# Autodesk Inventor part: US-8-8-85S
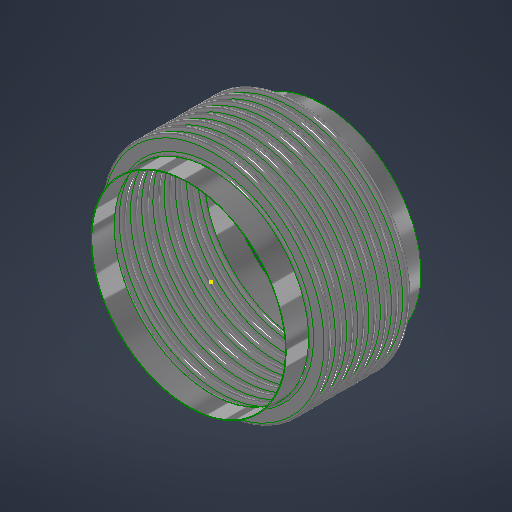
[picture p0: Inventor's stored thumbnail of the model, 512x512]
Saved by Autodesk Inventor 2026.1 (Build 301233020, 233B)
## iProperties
Category: 22 GA (0.030 THICK)
RuleStatus: InUse
Created: 2026-07
Part Number: US-8-8-85S
Project: =STOCK BELLOWS: <Stock Number><SFILL>
Material: ASTM A240-304
Description: =STOCK BELLOWS: <Stock Number>, <SID_> I.D., <SOD_> O.D., <SPLY_> PLY, <Category>, <SNET_CONS> CONS.<PITCH_><STANGENT_> TANGENT<SFILL>
Document SubType Name: Sheet Metal
Designer: LC
Stock Number: U.S-8-8-85S
Surface Area: 659.127 cm^2
Volume: 56.61 cm^3
Sheet Metal Rule: Default
Appearance: STAINLESS STEEL
NET_TUBE: 3.428
COUNTER: 1.500
PBAR: 1.214
PSET: 5.356
PLY: 2
CONS: 2
THK: 0.036
ID: 4.500
OD: 5.500
CONS_: 2
TANGENT: 0.500
PITCH: 0.375
BELLOWS_UPSET: 0.000
NET_CONS: 2
S_CONS: 0
Description_Units: 0
ID_M: 114.30 mm
OD_M: 139.70 mm
THK_M: 0.91 mm
ID_U: 4.500 in
OD_U: 5.500 in
THK_U: 0.036 in
TANGENT2: 0.500
d79: 1.000
d82: 1.000
d83: 26.000
d84: 24.000
d80: 2.571
d81: 10
SID: 2.375
SCONS_: 8
SPITCH: 0.250
SBELLOWS_UPSET: 0.000
SNET_CONS: 8
SS_CONS: 0
SCONS: 8
d174: 8
d177: 0.018
d178: 2.375
d179: 3.000
d180: 0.375
d181: 1.000
d182: 0.000
d190: 8
d191: 1
d192: 1
d193: 8
d194: 0
PART_NUMBER: U.S-8-8-85S
PRESSURE: 85
SIZE: 8.00
STANGENT_: 1.000
d214: 8
d217: 0.030
d218: 6.625
d219: 8.125
d220: 0.500
d221: 1.000
d222: 0.000
d230: 8
d231: 1
d232: 1
d233: 8
d234: 0
STANGENT: 4.000
SPLY_: 1
STHK_: 0.030
SID_: 8.625
SOD_: 10.125
SPITCH_: 0.500
STANGENT__: 1.000
SBELLOWS_UPSET_: 0.000
SDIFF_TAN: 1.000
TAN_TO_TAN: 0.750 in
d252: 2
d275: 2
d287: 0.050
d289: 0.500
d290: 0.000
d263: 2
d265: 1
d268: 2
d269: 0
d286: 2
d288: 1
d291: 2
d292: 0
SOD_NECK: 8 11/16
CFILL: .
SFILL: .
PITCH_: =, <SPITCH_> PITCH,
SREROLL: 0.750
MATTABLE: 20 GA (0.036 THICK)
MESH: ,
CSECT: 2
Author: LC
Keywords: 20 GA (0.036 THICK)
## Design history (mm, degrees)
sketch "Sketch2"
  geometry: L1 (0, -183.595)-(0, 600.956) reference; L2 (58.979, 0)-(57.15, 0); L3 (60.446, -1.467)-(66.554, -1.467); L4 (60.446, -3.296)-(66.554, -3.296); L5 (66.554, -8.058)-(60.446, -8.058); L6 (66.554, -6.229)-(60.446, -6.229); L7 (58.979, -9.525)-(57.15, -9.525); L8 (60.446, 0)-(60.446, -9.525); L9 (66.554, -4.762)-(69.85, -4.763); L10 (57.15, 0)-(57.15, -9.525); L11 (20.376, 102.841)-(20.376, 101.926); L12 (58.262, 488.877)-(58.262, 349.177); L13 (58.262, 479.352)-(58.262, 339.652); L14 (93.133, -58.817)-(93.133, -71.517); L15 (118.746, -66.401)-(118.746, -66.401); L16 (66.554, -6.229)-(66.554, -8.058); L17 (60.446, -6.229)-(60.446, -8.058); L18 (60.446, -7.144)-(66.554, -7.144); L19 (69.85, 0)-(69.85, -9.525); L20 (-66.554, -6.229)-(-66.554, -8.058); L21 (-66.554, -1.467)-(-60.446, -1.467); L22 (-66.554, -3.296)-(-60.446, -3.296); L23 (-60.446, -6.229)-(-66.554, -6.229); L24 (-66.554, -7.144)-(-60.446, -7.144); L25 (-60.446, -8.058)-(-66.554, -8.058); L26 (-60.446, -6.229)-(-60.446, -8.058); L27 (-57.15, -2.522)-(-57.15, -12.047); L28 (-60.446, -4.763)-(-57.15, -4.763); L29 (-66.554, 3.828)-(-66.554, -9.525); L30 (-68.021, 0)-(-69.85, 0); L31 (-69.85, 0)-(-69.85, -9.525); L32 (-68.021, -9.525)-(-69.85, -9.525); A1 r 1.467 centre (60.446, 0) between (58.979, 0) and (60.446, -1.467); A2 r 3.296 centre (60.446, 0) between (57.15, 0) and (60.446, -3.296); A3 r 3.296 centre (66.554, -4.762) between (66.554, -8.058) and (66.554, -1.467); A4 r 1.467 centre (66.554, -4.762) between (66.554, -6.229) and (66.554, -3.296); A5 r 1.467 centre (60.446, -9.525) between (60.446, -8.058) and (58.979, -9.525); A6 r 3.296 centre (60.446, -9.525) between (60.446, -6.229) and (57.15, -9.525); A7 r 2.381 centre (66.554, -4.762) between (66.554, -7.144) and (68.936, -4.762); A8 r 2.381 centre (60.446, -9.525) between (60.446, -7.144) and (58.064, -9.525); A9 r 1.467 centre (-66.554, -9.525) between (-66.554, -8.058) and (-68.021, -9.525); A10 r 1.467 centre (-60.446, -4.763) between (-60.446, -6.229) and (-60.446, -3.296); A11 r 2.381 centre (-60.446, -4.763) between (-60.446, -7.144) and (-58.064, -4.763); A12 r 3.296 centre (-60.446, -4.763) between (-60.446, -8.058) and (-60.446, -1.467); A13 r 2.381 centre (-66.554, -9.525) between (-66.554, -7.144) and (-68.936, -9.525); A14 r 3.296 centre (-66.554, -9.525) between (-66.554, -6.229) and (-69.85, -9.525); A15 r 1.467 centre (-66.554, 0) between (-68.021, 0) and (-66.554, -1.467); A16 r 3.296 centre (-66.554, 0) between (-69.85, 0) and (-66.554, -3.296); 10 further points
  constraints: 62 end point, 38 point on circle, 20 tangent, 16 centre point, 12 parallel, 9 midpoint, 7 vertical, 6 coincident, 6 concentric, 6 point on line, 4 equal radius, 4 perpendicular, 3 horizontal, 1 collinear, 1 horizontal alignment, 10 other
  dimensions: "THK" = 0.9144 distance of L11.start L11.end; "ID" = 114.3 distance of L11.end point (20.376, -12.374); "OD" = 139.7 distance of L12.start L12.end; "PITCH" = 9.525 distance of L12.start L13.start; "TANGENT" = 12.7 distance of L14.start L14.end; "BELLOWS_UPSET" = 0 distance of L15.start L15.end; "d43" = 114.3 diameter of L10 L1 (= ID); "d44" = 139.7 diameter of L9.end L1 (= OD); "d45" = 1.8288 distance between parallel lines of L5 L6 (computed from THK, PLY); "d46" = 3.29565 radius of A3 (computed from PITCH, THK, PLY); "UPSET_PITCH" = 9.525 distance of L2.end L7.end (derived); "SIDEWALL_ANGLE" = 0 deg angle of L3 L9 (derived); "CON_GAP" = 2.9337 distance of point (60.446, -6.229) point (60.446, -3.296) (derived); "TAN1" = 3.74046 dimension on A8 (derived); "TAN2" = 3.74046 dimension on A7 (derived); "LEG1" = 6.1087 distance of L18.start L18.end (derived); "d278" = 1.8288 distance between parallel lines of L25 L23 (derived); "d279" = 3.29565 radius of A12 (derived); "d280" = 9.525 distance of L30.end L31.end (derived); "d281" = 360 deg dimension on L21 L28 (derived); "d282" = 2.9337 distance of point (-66.554, -6.229) point (-66.554, -3.296) (derived); "d283" = 3.74046 dimension on A13 (derived); "d284" = 3.74046 dimension on A11 (derived); "d285" = 6.1087 distance of L24.start L24.end (derived); "d293" = 114.3 diameter of L27 L1 (derived); "d294" = 139.7 diameter of L31 L1 (derived)
  node "Sketch Rectangular Pattern1" dims "d31" = 25.4, "ID" = 114.3
  node "Sketch Rectangular Pattern2" dims "d39" = 25.4, "PITCH" = 9.525
revolve "CONS" stored, may be unused: angle "d48" = 90 deg
node "BELLOW MIDPLANE"
pattern_linear "Rectangular Pattern2" dims "d52" = 9.525 (= UPSET_PITCH)
sketch "Sketch5"
  geometry: C1 r 58.979 at (0, 0) reference; C2 r 57.15 at (0, 0) reference
extrude "TANGENT" new body sketch "Sketch5" distance "d53" = 12.7 (= TANGENT); taper "d54" = 0 deg
revolve "SAMETAN" stored, may be unused: angle "d65" = 90 deg
revolve "DIFFTAN" stored, may be unused: angle "d70" = 90 deg
sketch "Sketch9"
  geometry: L1 (58.391, 0)-(-58.391, 0) reference; L2 (0, -17.78)-(0, 17.78) reference; L3 (41.708, 0)-(-41.708, 0); L4 (41.708, -11.906)-(41.708, 11.906); L5 (29.008, -11.906)-(29.008, 11.906); L6 (15.418, 11.906)-(15.418, -11.906); L7 (-29.008, -11.906)-(-29.008, 11.906); L8 (-41.708, -11.906)-(-41.708, 11.906); L9 (40.914, -11.906)-(40.914, 11.906); L10 (41.708, -11.906)-(40.914, -11.906); L11 (41.708, 11.906)-(40.914, 11.906); L12 (15.815, 11.906)-(15.022, 11.906); L13 (15.022, 11.906)-(15.022, -11.906); L14 (15.022, -11.906)-(15.815, -11.906); L15 (15.815, -11.906)-(15.815, 11.906); L16 (-15.815, 11.906)-(-15.815, -11.906); L17 (-15.418, 11.906)-(-15.418, -11.906); L18 (-15.815, -11.906)-(-15.022, -11.906); L19 (-15.022, -11.906)-(-15.022, 11.906); L20 (-15.022, 11.906)-(-15.815, 11.906); L21 (-41.708, -11.906)-(-40.914, -11.906); L22 (-40.914, -11.906)-(-40.914, 11.906); L23 (-40.914, 11.906)-(-41.708, 11.906); L24 (-41.708, 11.906)-(-41.708, -11.906); L25 (41.708, -0.397)-(-41.708, -0.397); L26 (-41.708, -0.397)-(-41.708, 0.397); L27 (-41.708, 0.397)-(41.708, 0.397); L28 (41.708, 0.397)-(41.708, -0.397); L29 (-41.708, 11.906)-(41.708, 11.906); L30 (41.708, 11.906)-(41.708, 12.7); L31 (41.708, 12.7)-(-41.708, 12.7); L32 (-41.708, 12.7)-(-41.708, 11.906); L33 (41.708, -11.906)-(-41.708, -11.906); L34 (-41.708, -11.906)-(-41.708, -12.7); L35 (-41.708, -12.7)-(41.708, -12.7); L36 (41.708, -12.7)-(41.708, -11.906); 30 further points
  constraints: 68 end point, 13 midpoint, 13 parallel, 8 horizontal, 7 perpendicular, 6 equal length, 3 point on line, 2 vertical, 14 other
  dimensions: "d115" = 23.8125 distance of L4.start L4.end (derived); "d116" = 12.7 distance between parallel lines of L4 L5 (derived); "d117" = 13.58962 distance between parallel lines of L5 L6 (derived); "d125" = 44.42645 distance between parallel lines of L7 L6 (derived); "d127" = 12.7 distance between parallel lines of L8 L7 (derived); "d128" = 26.28962 distance between parallel lines of L6 L4 (derived); "d130" = 83.41607 distance between parallel lines of L8 L4 (derived); "RULER_THK" = 0.79375 distance between parallel lines of L4 L9; "d135" = 0.79375 distance of L13.end L14.end (derived); "d138" = 30.83684 distance of L13.end L16.end (derived); "d143" = 0.79375 distance of L22.end L8.end (derived); "d144" = 0.79375 distance between parallel lines of L27 L25 (derived)
extrude "RULER" join sketch "Sketch9" distance "d149" = 0.79375 (derived); taper "d150" = 0 deg
extrude "BARS" join sketch "Sketch9" distance "d151" = 0.79375 (derived); taper "d152" = 0 deg
pattern_linear "Rectangular Pattern4" dims "d155" = 30.83684 (derived)
sketch "Sketch13"
  geometry: L1 (93.149, -52.467)-(93.149, -77.867); L2 (110.299, 0)-(109.537, 0); L3 (110.299, -12.7)-(109.537, -12.7); L4 (125.031, -9.906)-(113.094, -9.906); L5 (125.031, -9.144)-(113.093, -9.144); L6 (125.031, -6.35)-(128.588, -6.35); L7 (113.093, -2.794)-(125.031, -2.794); L8 (113.093, 0)-(113.094, -12.7); L9 (109.537, 0)-(109.537, -12.7); L10 (58.254, -312.281)-(58.254, -569.456); L11 (58.254, -324.981)-(58.254, -582.156); L12 (58.254, -350.381)-(58.254, -607.556); L13 (58.254, -363.081)-(58.254, -620.256); L14 (58.254, -375.781)-(58.254, -632.956); L15 (58.254, -388.481)-(58.254, -645.656); L16 (58.254, -401.181)-(58.254, -658.356); L17 (58.254, -337.681)-(58.254, -594.856); L18 (20.376, 102.688)-(20.376, 101.926); L19 (113.094, -3.556)-(125.031, -3.556); L20 (0, -769.925)-(0, 248.124) reference; L21 (-23.752, 0)-(142.514, 0) reference; A1 r 2.794 centre (113.093, 0) between (110.299, 0) and (113.093, -2.794); A2 r 2.794 centre (113.094, -12.7) between (113.094, -9.906) and (110.299, -12.7); A3 r 3.556 centre (113.094, -12.7) between (113.093, -9.144) and (109.537, -12.7); A4 r 2.794 centre (125.031, -6.35) between (125.031, -9.144) and (125.031, -3.556); A5 r 3.556 centre (125.032, -6.35) between (125.031, -9.906) and (125.031, -2.794); A6 r 3.556 centre (113.093, 0) between (109.537, 0) and (113.094, -3.556); 6 further points; 1 other entity
  constraints: 38 end point, 15 point on circle, 9 tangent, 6 centre point, 6 parallel, 5 vertical alignment, 4 point on line, 4 vertical, 3 coincident, 3 concentric, 2 collinear, 2 equal radius, 1 horizontal, 1 perpendicular, 23 other
  dimensions: "SBELLOWS_UPSET_" = 0 distance of point (118.762, -66.401) point (118.762, -66.401); "STOTAL_THK_BELLOW__" = 0.762 distance between parallel lines of L4 L5 (derived); "d224" = 3.556 radius of A5 (derived); "d225" = 12.7 distance of L2.end L3.end (derived); "SSIDEWALL_ANGLE_" = 0 deg angle of L7 L6 (derived); "SSCON_GAP_" = 5.588 distance of point (113.094, -9.144) point (113.094, -3.556) (derived); "d235" = 219.075 diameter of L9 L20 (derived); "d236" = 257.175 diameter of L6.end L20 (derived)
  node "Sketch Rectangular Pattern4" dims "d228" = 25.4
  node "Sketch Rectangular Pattern5" dims "d229" = 25.4
revolve "SBELLOW" stored, may be unused: angle "d197" = 90 deg
pattern_linear "Rectangular Pattern5" dims "d204" = 12.7 (derived)
revolve "STANGENT" stored, may be unused: angle "d240" = 90 deg
revolve "SSAMETAN" stored, may be unused: angle "d241" = 90 deg
revolve "SDIFFTAN" stored, may be unused: angle "d246" = 90 deg
revolve "INVCON" stored, may be unused: angle "d295" = 90 deg
pattern_linear "Rectangular Pattern6" dims "d298" = 9.525 (derived)
revolve "INVTANGENT" stored, may be unused: angle "d302" = 90 deg
revolve "INVSAMETAN" stored, may be unused: angle "d307" = 90 deg
revolve "INVDIFFTAN" stored, may be unused: angle "d312" = 90 deg
sketch "ID BELLOW MOUNT CALC"
  geometry: L1 (44.45, 0)-(38.1, 0); L2 (38.1, 0)-(38.1, 12.7); L3 (38.1, 12.7)-(44.45, 12.7); L4 (44.45, 12.7)-(44.45, 0); L5 (36.513, 12.7)-(34.684, 12.7); L6 (34.684, 12.7)-(34.684, 0); L7 (34.684, 0)-(36.513, 0); L8 (36.513, 0)-(36.513, 12.7); L9 (0, -2.54)-(0, 15.24) reference; L10 (-8.89, 0)-(53.34, 0) reference; 1 further point
  constraints: 16 end point, 5 parallel, 2 collinear, 2 horizontal, 2 perpendicular
  dimensions: "d314" = 12.7 distance of L5.end L6.end (derived); "d315" = 1.8288 distance of L5.start L5.end (derived); "IG" = 1.5875 distance between parallel lines of L2 L8; "PIPE_OD" = 88.9 diameter of L4 L9; "PIPE_WALL" = 6.35 distance of L2.end L3.end; "ID_MT_BELLOW" = 69.3674 diameter of L6 L9 (derived)
revolve "CFILL" stored, may be unused: angle "d320" = 90 deg
pattern_linear "Rectangular Pattern7" dims "d323" = 9.525 (derived)
revolve "SFILL" stored, may be unused: angle "d324" = 90 deg
pattern_linear "Rectangular Pattern8" dims "d327" = 12.7 (derived)
node "STOCK BELLOW MIDPLANE"
sketch "Sketch21"
  geometry: L1 (0, -100.013)-(0, 100.013) reference; L2 (-100.013, 0)-(100.013, 0) reference; L3 (-0.099, 71.437)-(0.099, 71.437); L4 (0.099, 71.437)-(0.099, 55.562); L5 (0.099, 55.562)-(-0.099, 55.562); L6 (-0.099, 55.562)-(-0.099, 71.437); C1 r 55.562 at (0, 0); C2 r 71.437 at (0, 0); 3 further points
  constraints: 8 end point, 2 centre point, 2 coincident, 2 parallel, 2 tangent, 1 horizontal, 1 perpendicular, 1 other
  dimensions: "d329" = 111.125 diameter of C1 (derived); "d330" = 142.875 diameter of C2 (derived); "d331" = 0.19844 distance of L3.start L3.end
extrude "CLAMSHELL" cut sketch "Sketch21" extent not by distance; stored distance "d332" = 0; taper "d333" = 0 deg
pattern_circular "Circular Pattern1" dims angle "d335" = 180 deg (derived)
node "BELLOW"
sketch "Sketch6"
  geometry: L1 (-19.05, 58.979)-(-6.35, 58.979); L2 (-6.35, 58.979)-(-6.35, 57.15); L3 (-6.35, 57.15)-(-19.05, 57.15); L4 (-19.05, 57.15)-(-19.05, 58.979); L5 (2.54, 0)-(-59.69, 0) reference; L6 (-38.1, -108.388)-(-38.1, 156.601) reference; 1 further point
  constraints: 8 end point, 2 parallel, 1 horizontal, 1 perpendicular
  dimensions: "d61" = 12.7 distance of L2.end L3.end (derived); "d62" = 1.8288 distance of L1.end L2.end (derived); "d63" = 114.3 diameter of L3 L5 (derived); "d64" = 19.05 distance between parallel lines of L4 L6 (derived)
sketch "Sketch12"
  geometry: 1 further point
sketch "Sketch14"
  geometry: L1 (-25.4, 110.299)-(0, 110.299); L2 (0, 110.299)-(0, 109.537); L3 (0, 109.537)-(-25.4, 109.537); L4 (-25.4, 109.537)-(-25.4, 110.299); L5 (5.08, 0)-(-30.48, 0) reference; L6 (0, -16.98)-(0, 101.879) reference; 1 further point
  constraints: 8 end point, 2 parallel, 1 collinear, 1 horizontal, 1 perpendicular
  dimensions: "d237" = 0.762 distance of L3.end L1.start (derived); "d238" = 219.075 diameter of L3 L5 (derived); "d239" = 25.4 distance of L1.start L1.end (derived); "SOD_NECK" = 220.599 diameter of L1 L5 (derived)
sketch "Sketch15"
  geometry: L1 (-16.98, 0)-(101.879, 0) reference; L2 (109.538, -101.6)-(110.3, -101.6); L3 (110.3, -101.6)-(110.3, -127); L4 (110.3, -127)-(109.538, -127); L5 (109.538, -127)-(109.538, -101.6); L6 (0, -154.94)-(0, 40.64) reference; 1 further point
  constraints: 8 end point, 2 parallel, 1 horizontal, 1 perpendicular
  dimensions: "d205" = 25.4 distance of L4.end L2.start (derived); "d206" = 0.762 distance of L3.end L4.end (derived); "d207" = 219.075 diameter of L5 L6 (derived); "d208" = 101.6 distance between parallel lines of L1 L2 (derived)
node "TANGENT_"
node "SAME_TAN"
sketch "Sketch8"
  geometry: L1 (58.979, -19.05)-(57.15, -19.05); L2 (57.15, -19.05)-(57.15, -31.75); L3 (57.15, -31.75)-(58.979, -31.75); L4 (58.979, -31.75)-(58.979, -19.05); L5 (0, -40.64)-(0, 21.59) reference; L6 (-108.388, 0)-(156.601, 0) reference; 1 further point
  constraints: 8 end point, 2 parallel, 1 horizontal, 1 perpendicular
  dimensions: "d66" = 114.3 diameter of L2 L5 (derived); "TOTAL_THK_BELLOW" = 1.8288 distance of L2.end L3.end (derived); "d68" = 19.05 distance between parallel lines of L1 L6 (derived); "d69" = 12.7 distance of L1.end L2.end (derived)
node "DIFF_TAN"
node "Sketch Rectangular Pattern3" dims "d138" = 30.83684 (derived), "d141" = 25.4
node "SBELLOW_"
node "STANGENT_"
node "SSAME_TAN"
sketch "Sketch16"
  geometry: L1 (110.299, -101.6)-(109.537, -101.6); L2 (109.537, -101.6)-(109.537, -127); L3 (109.537, -127)-(110.299, -127); L4 (110.299, -127)-(110.299, -101.6); L5 (0, -154.94)-(0, 40.64) reference; L6 (-16.98, 0)-(101.879, 0) reference; 1 further point
  constraints: 8 end point, 2 parallel, 1 horizontal, 1 perpendicular
  dimensions: "SDIFF_TAN" = 25.4 distance of L3.end L1.start; "d243" = 0.762 distance of L2.end L3.end (derived); "d244" = 101.6 distance between parallel lines of L1 L6 (derived); "d245" = 219.075 diameter of L2 L5 (derived)
node "SDIFF_TAN"
body "Solid15"
sketch "Sketch17"
  geometry: L1 (69.85, 12.7)-(68.021, 12.7); L2 (68.021, 12.7)-(68.021, 0); L3 (68.021, 0)-(69.85, 0); L4 (69.85, 0)-(69.85, 12.7); L5 (0, -2.54)-(0, 15.24) reference; L6 (-13.97, 0)-(83.82, 0) reference; 2 further points
  constraints: 8 end point, 2 parallel, 1 horizontal, 1 midpoint, 1 perpendicular, 1 point on line
  dimensions: "INVTANGENT" = 12.7 distance of L3.end L1.start (derived); "d300" = 1.8288 distance of L1.start L1.end (derived); "d301" = 139.7 diameter of L4 L5 (derived)
body "Solid16"
sketch "Sketch18"
  geometry: L1 (69.85, -19.05)-(68.021, -19.05); L2 (68.021, -19.05)-(68.021, -31.75); L3 (68.021, -31.75)-(69.85, -31.75); L4 (69.85, -31.75)-(69.85, -19.05); L5 (-13.97, 0)-(83.82, 0) reference; L6 (0, -40.64)-(0, 21.59) reference; 1 further point
  constraints: 8 end point, 2 parallel, 1 horizontal, 1 perpendicular
  dimensions: "d303" = 19.05 distance between parallel lines of L1 L5 (derived); "d304" = 12.7 distance of L3.end L1.start (derived); "d305" = 1.8288 distance of L2.end L3.end (derived); "d306" = 139.7 diameter of L4 L6 (derived)
body "Solid17"
sketch "Sketch19"
  geometry: L1 (69.85, -19.05)-(68.021, -19.05); L2 (68.021, -19.05)-(68.021, -31.75); L3 (68.021, -31.75)-(69.85, -31.75); L4 (69.85, -31.75)-(69.85, -19.05); L5 (0, -40.64)-(0, 21.59) reference; L6 (-13.97, 0)-(83.82, 0) reference; 1 further point
  constraints: 8 end point, 2 parallel, 1 horizontal, 1 perpendicular
  dimensions: "d308" = 12.7 distance of L1.end L2.end (derived); "d309" = 139.7 diameter of L4 L5 (derived); "d310" = 1.8288 distance of L2.end L3.end (derived); "d311" = 19.05 distance between parallel lines of L1 L6 (derived)
body "Solid18"
body "Solid19"
body "Solid20"
other parameters: "BMPL" = -50.8, "PSET" = 136.0424 (computed from OD, THK, PLY) [user parameter], "PBAR" = 30.83684 (= 0.570796 x PITCH + OD - ID) [user parameter; used in 1 equation term], "COUNTER" = 15 [user parameter], "NET_TUBE" = 87.07367 (computed from CONS_, PBAR, TANGENT) [user parameter], "S_CONS" = 0 [user parameter; used in 1 equation term], "ID_M" = 114.3 (= ID) [user parameter], "OD_M" = 139.7 (= OD) [user parameter], "THK_M" = 0.9144 (= THK) [user parameter], "ID_U" = 114.3 (= ID) [user parameter], "OD_U" = 139.7 (= OD) [user parameter], "THK_U" = 0.9144 (= THK) [user parameter], "D_UNITS" = 0 [user parameter], "TANGENT2" = 12.7 [user parameter], "TAN_TO_TAN" = 19.05 [user parameter], "OD_NECK" = 117.9576 [user parameter], "d79" = 25.4, "d80" = 65.29823 [user parameter], "d82" = 25.4, "d83" = 660.4, "d84" = 609.6, "sa_0" = 4, "FRAME_THK" = 0.79375 [user parameter], "CON_FLAT" = 13.58962 [user parameter], "SID" = 60.325 [user parameter], "SPITCH" = 6.35 [user parameter], "STANGENT_" = 25.4 [user parameter], "SBELLOWS_UPSET" = 0 [user parameter], "SS_CONS" = 0 [user parameter], "STAN_TO_TAN_" = 101.6 [user parameter], "d100" = 0.762 [user parameter], "d191" = 25.4 [user parameter], "d194" = 0 [user parameter], "STANGENT" = 101.6 [user parameter], "d234" = 0 [user parameter], "SUPSET_PITCH_" = 12.7 [user parameter], "d269" = 0 [user parameter], "d287" = 1.27, "d289" = 12.7, "d290" = 0, "d292" = 0 [user parameter], "Thickness" = 3.048 (derived), "KFactor" = 4.4, "BendRadius" = 3.048 (derived), "BendReliefWidth" = 3.048 (derived), "BendReliefDepth" = 1.524 (derived), "CornerReliefSize" = 12.192 (derived), "SeamGap" = 0.00508, "MinimumRemnant" = 6.096 (derived), "TransitionRadius" = 3.048 (derived), "JacobiRadiusSize" = 3.048 (derived), "GapSize" = 3.048 (derived), "SREROLL" = 19.05 [user parameter], "CUR_STK_PITCH" = 12.7 [user parameter], "d328" = -50.8 (derived), "CSECTDEG" = 180 deg [user parameter]
